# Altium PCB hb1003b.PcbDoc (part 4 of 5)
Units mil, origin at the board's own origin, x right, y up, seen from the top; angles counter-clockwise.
Board outline 2757 x 3548 mil, 2 copper layers (Top Layer, Bottom Layer); 120 components, 120 nets, 466 pads, 329 vias.
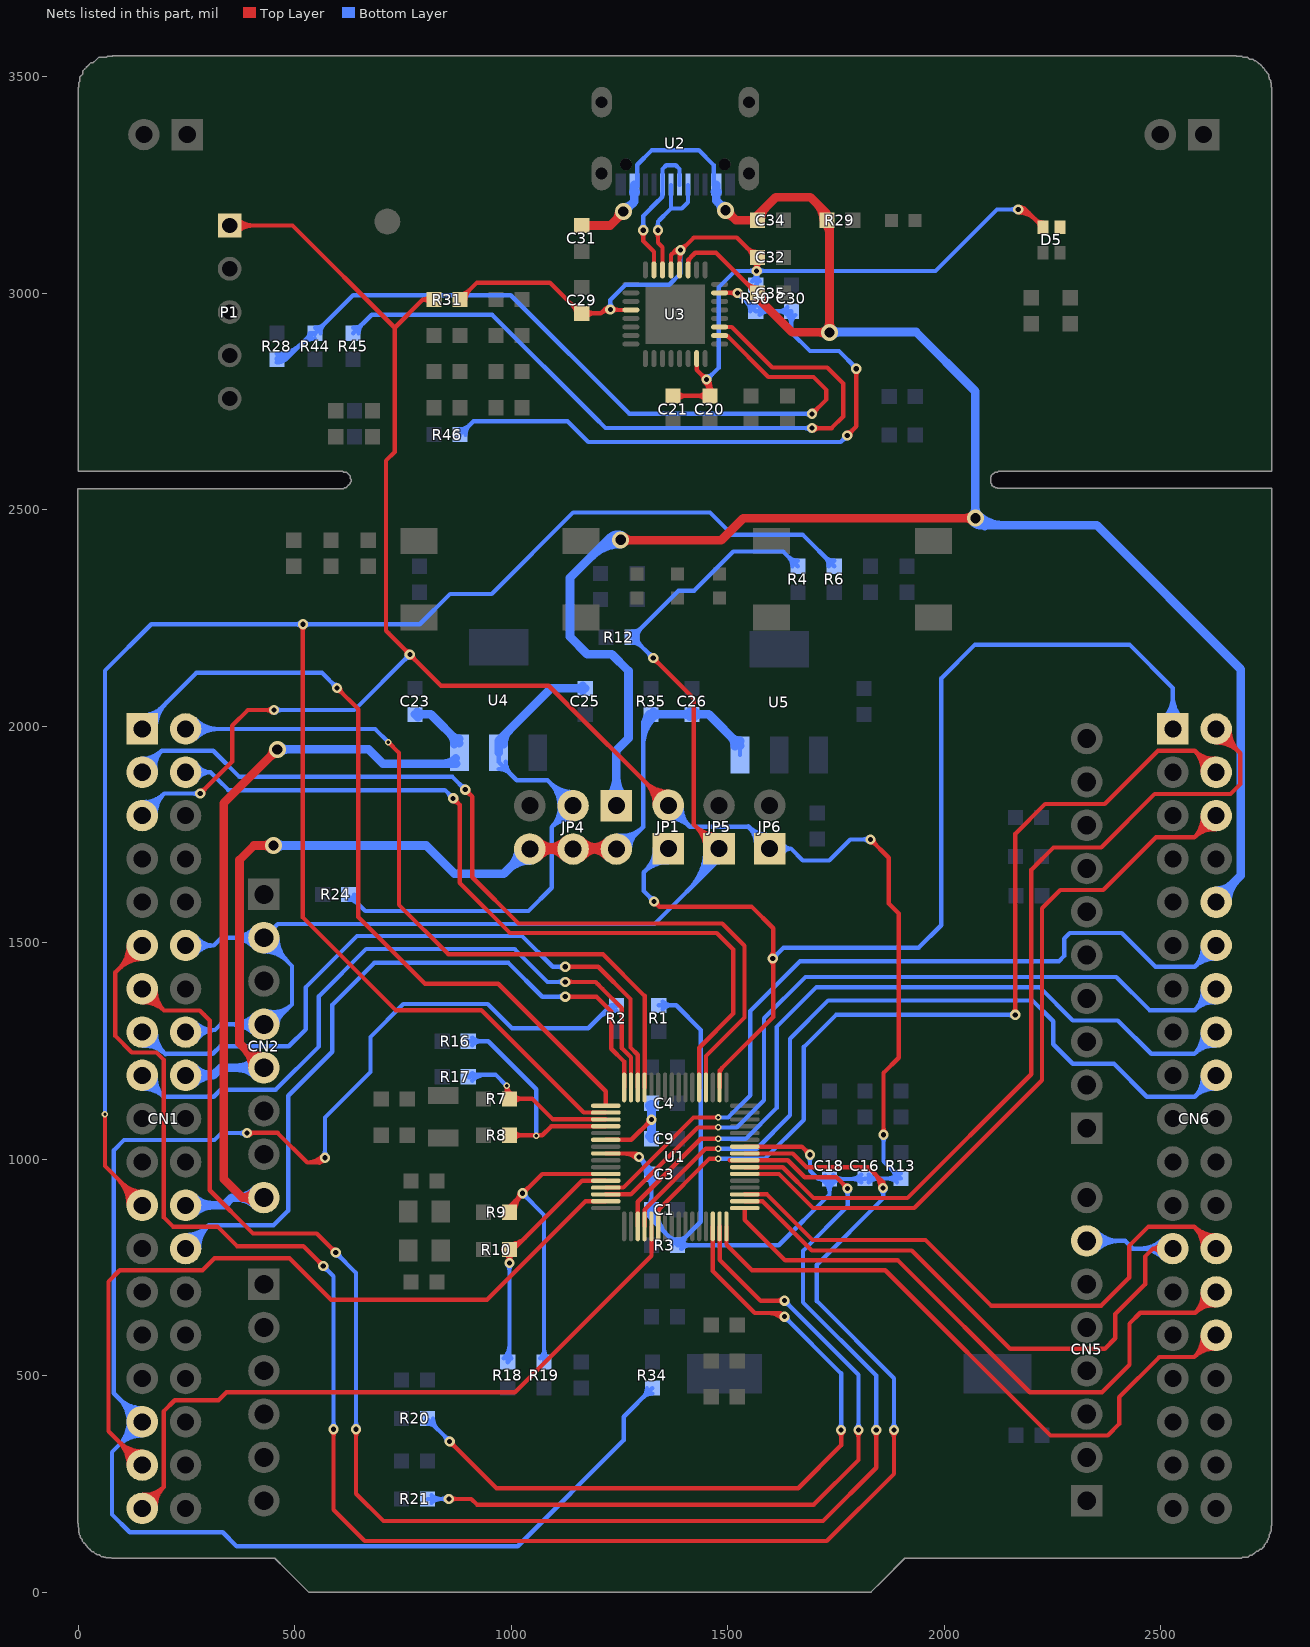
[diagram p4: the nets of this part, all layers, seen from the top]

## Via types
v1: diameter 23.62, hole 11.81, Top Layer to Bottom Layer, tented both sides, 290 vias
v2: diameter 39.37, hole 23.62, Top Layer to Bottom Layer, tented both sides, 29 vias
v3: diameter 15, hole 8, Top Layer to Bottom Layer, tented both sides, 10 vias

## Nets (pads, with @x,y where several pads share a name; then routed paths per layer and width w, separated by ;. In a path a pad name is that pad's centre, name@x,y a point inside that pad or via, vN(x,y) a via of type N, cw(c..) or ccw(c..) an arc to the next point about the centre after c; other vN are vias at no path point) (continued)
PB10: R20.2 U1.30 | length 1956.9
  Top Layer w10: v1@858,341.19 cw(c858,324.75) 869.63,336.37 cw(c881.25,348) v1@864.81,348 ; v1(858,348) 966,240 1663,240 1762,339 v1(1762,374) ; U1.30@1465.61,844.57 1465.61,741.39 1562.5,644.5 1622.5,644.5 v1(1631,636) ; 1594.04,644.5 cw(c1594.04,599.04) v1@1626.18,631.18 ; 1618.18,644.5 cw(c1618.18,623.18) v1@1633.25,638.25 ; v1@1757.18,369.18 cw(c1745.56,357.56) 1762,357.56 cw(c1778.44,357.56) v1@1766.82,369.18
  Bottom Layer w10: R20.2@805,401 v1@858.5,347.5 ; R20.2@807,388.5 cw(c807,363.16) 824.92,381.08 ; R20.2@819.5,401 ccw(c854.51,401) 829.75,376.25 ; v1@851.19,348 ccw(c834.75,348) 846.37,359.63 ccw(c858,371.25) v1@858,354.81 ; v1@1631,629.19 cw(c1631,612.75) 1642.63,624.37 cw(c1654.25,636) v1@1637.81,636 ; v1(1631,636) 1762,505 v1@1762,375 ; v1@1757.18,378.82 ccw(c1745.56,390.44) 1762,390.44 ccw(c1778.44,390.44) v1@1766.82,378.82
PB11: R21.2 U1.31 | length 1950
  Top Layer w10: v1(856,215) 908,215 921,202 1699,202 1802,305 v1(1802,374) ; v1@860.82,210.18 cw(c872.44,198.56) 872.44,215 cw(c872.44,231.44) v1@860.82,219.82 ; U1.31@1481.36,844.57 1481.36,767.64 1576,673 v1(1631,673) ; v1@1626.18,668.18 ccw(c1614.56,656.56) 1614.56,673 ccw(c1614.56,689.44) v1@1626.18,677.82 ; v1@1797.18,369.18 cw(c1785.56,357.56) 1802,357.56 cw(c1818.44,357.56) v1@1806.82,369.18
  Bottom Layer w10: R21.2@807,215 v1(856,215) ; R21.2@815.84,206.16 cw(c837.18,184.83) 837.18,215 cw(c837.18,245.18) R21.2@815.84,223.84 ; v1@851.18,210.18 ccw(c839.56,198.56) 839.56,215 ccw(c839.56,231.44) v1@851.18,219.82 ; v1@1631,666.19 cw(c1631,649.75) 1642.63,661.37 cw(c1654.25,673) v1@1637.81,673 ; v1(1631,673) 1802,502 v1(1802,374) ; v1@1797.18,378.82 ccw(c1785.56,390.44) 1802,390.44 ccw(c1818.44,390.44) v1@1806.82,378.82
PB12: CN6.30 U1.32 | length 1675.1
  Top Layer w10: U1.32@1497.11,844.57 1497.11,801.89 1556,743 1864,743 2245.42,361.58 2377.58,361.58 2404,388 2404,450 2497,543 2577.77,543 ; CN6.30@2596.62,591.74 cw(c2532.11,588.67) 2577.77,543 ; CN6.30@2606.61,592.21 cw(c2562.63,590.12) 2593.76,558.99 cw(c2624.89,527.86) CN6.30@2626.98,571.83 ; CN6.30@2625,595 CN6.30@2631,595 ; CN6.30@2626.51,561.85 ccw(c2623.44,497.34) 2577.77,543 ; CN6.30@2628,593.23 2577.77,543
PB13: CN6.28 U1.33 | length 1601.7
  Top Layer w10: U1.33@1539.43,886.89 1539.43,859.57 1633,766 1893,766 2197.42,461.58 2364.58,461.58 2428,525 2428,620 2453,645 2579.77,645 ; CN6.28@2596.68,690.78 cw(c2538.54,686.24) 2579.77,645 ; CN6.28@2606.65,691.56 cw(c2567.01,688.46) 2595.12,660.35 cw(c2623.24,632.24) CN6.28@2626.33,671.88 ; CN6.28@2625.55,661.91 ccw(c2621.01,603.77) 2579.77,645 ; CN6.28@2628,693.23 2579.77,645
PB14: CN5.7 CN6.25 U1.34 | length 1946.6
  Top Layer w10: U1.34@1539.43,902.64 1580.36,902.64 1694,789 1925,789 2152.42,561.58 2370.58,561.58 2395,586 2395,642 2464,711 2464,775 2482.23,793.23 ; CN6.25@2498.68,781.93 ccw(c2482.23,775.6) 2482.23,793.23 ; CN6.25@2498.68,804.52 cw(c2482.23,810.86) 2482.23,793.23 ; CN6.25@2528,793.23 2482.23,793.23
  Bottom Layer w10: CN5.7@2328,811 CN5.7@2329,811 2418,811 2431,798 2435.77,793.23 CN6.25@2528,793.23 ; CN5.7@2344.14,795.86 cw(c2380.71,759.29) 2380.71,811 cw(c2380.71,862.71) CN5.7@2344.14,826.14 ; CN5.7@2351.22,788.78 cw(c2404.85,735.15) 2404.85,811 cw(c2404.85,886.85) CN5.7@2351.22,833.22 ; CN6.25@2505.78,771.01 ccw(c2452.15,717.38) 2452.15,793.23 ccw(c2452.15,869.08) CN6.25@2505.78,815.44 ; CN6.25@2512.86,778.08 ccw(c2476.29,741.52) 2476.29,793.23 ccw(c2476.29,844.93) CN6.25@2512.86,808.37
PB15: CN6.26 U1.35 | length 1518.3
  Top Layer w10: U1.35@1539.43,918.39 1590.61,918.39 1696,813 1957,813 2108.42,661.58 2362.58,661.58 2427,726 2427,799 2472,844 2550,844 2577.23,844 ; CN6.26@2596.61,794.47 ccw(c2530.33,797.09) 2577.23,844 ; CN6.26@2606.6,794.07 ccw(c2561.42,795.86) 2593.39,827.84 ccw(c2625.37,859.81) CN6.26@2627.15,814.63 ; CN6.26@2626.76,824.62 cw(c2624.14,890.9) 2577.23,844 ; CN6.26@2628,793.23 2577.23,844
PC0: CN6.12 U1.13 | length 2024.9
  Top Layer w10: U1.13@1218.57,934.13 1259.13,934.13 1421,1096 v3(1478,1096)
  Bottom Layer w10: v3@1477,1096 v3(1478,1096) 1501,1096 1552,1147 1552,1342 1667,1457 2265,1457 2277,1469 2277,1509 2290,1522 2410,1522 2488,1444 2578.77,1444 ; CN6.12@2596.64,1491.27 cw(c2535.34,1487.43) 2578.77,1444 ; CN6.12@2606.62,1491.89 cw(c2564.84,1489.28) 2594.44,1459.67 cw(c2624.05,1430.06) CN6.12@2626.66,1471.85 ; CN6.12@2626.04,1461.87 ccw(c2622.2,1400.57) 2578.77,1444 ; CN6.12@2628,1492.54 CN6.12@2628,1493.23 ; CN6.12@2628,1498 CN6.12@2628,1493.23 ; 2578.77,1444 CN6.12@2628,1493.23
PC1: CN6.14 U1.14 | length 1988.3
  Top Layer w10: U1.14@1218.57,918.39 1276.39,918.39 1431,1073 v3(1478,1073)
  Bottom Layer w10: v3(1478,1073) 1521,1073 1584,1136 1584,1325 1679.58,1420.58 2329,1420.58 ; 2309.77,1420.58 2329,1420.58 ; 2348.23,1420.58 2338,1420.58 ; CN6.14@2596.64,1391.27 cw(c2535.34,1387.43) 2578.77,1344 ; CN6.14@2606.62,1391.89 cw(c2564.84,1389.28) 2594.44,1359.67 cw(c2624.05,1330.06) CN6.14@2626.66,1371.85 ; CN6.14@2625.61,1395.61 CN6.14@2628,1398 ; CN6.14@2626.04,1361.87 ccw(c2622.2,1300.57) 2578.77,1344 ; CN6.14@2628,1393.23 2578.77,1344 ; 2329,1420.58 2338,1420.58 ; 2338,1420.58 2397.42,1420.58 2474,1344 2578.77,1344
PC2: CN1.35 U1.15 | length 1961.4
  Top Layer w10: CN1.35@116.58,293.23 ccw(c40.73,293.23) 94.37,346.86 ccw(c148,400.49) CN1.35@148,324.65 ; CN1.35@126.58,293.23 ccw(c74.88,293.23) 111.44,329.79 ccw(c148,366.35) CN1.35@148,314.65 ; CN1.35@148,293.23 70,371.23 70,717 96,743 287,743 315,771 488,771 584,675 944,675 1171.64,902.64 U1.15@1218.57,902.64
PC3: CN6.16 U1.19 | length 1976.2
  Top Layer w10: U1.19@1292.39,844.57 1292.39,901.39 1438,1047 v3(1478,1047)
  Bottom Layer w10: v3(1478,1047) 1542,1047 1613,1118 1613,1305 1705,1397 2220,1397 2297,1320 2401,1320 2478,1243 2577.77,1243 ; CN6.16@2596.62,1291.74 cw(c2532.11,1288.67) 2577.77,1243 ; CN6.16@2606.61,1292.21 cw(c2562.63,1290.12) 2593.76,1258.99 cw(c2624.89,1227.86) CN6.16@2626.98,1271.83 ; CN6.16@2625.61,1295.61 CN6.16@2628,1298 ; CN6.16@2626.51,1261.85 ccw(c2623.44,1197.34) 2577.77,1243 ; CN6.16@2628,1293.23 2577.77,1243
PC4: CN6.18 U1.20 | length 2001
  Top Layer w10: U1.20@1308.05,874.09 cw(c1329.69,874.09) 1314.39,889.39 ; U1.20@1308.13,844.57 1308.13,883.13 1449,1024 v3(1478,1024)
  Bottom Layer w10: v3(1478,1024) 1567,1024 1644,1101 1644,1278 1732,1366 2204,1366 2252,1318 2252,1265 2297,1220 2392,1220 2468,1144 2578.77,1144 ; CN6.18@2596.64,1191.27 cw(c2535.34,1187.43) 2578.77,1144 ; CN6.18@2606.62,1191.89 cw(c2564.84,1189.28) 2594.44,1159.67 cw(c2624.05,1130.06) CN6.18@2626.66,1171.85 ; CN6.18@2625.61,1195.61 CN6.18@2628,1198 ; CN6.18@2626.04,1161.87 ccw(c2622.2,1100.57) 2578.77,1144 ; CN6.18@2628,1193.23 2578.77,1144
PC5: CN1.37 U1.21 | length 1763.9
  Top Layer w10: CN1.37@148,193.23 197.42,242.65 ; CN1.37@149.28,214.61 ccw(c151.79,256.81) 181.69,226.91 ccw(c211.58,197.02) CN1.37@169.38,194.5 ; CN1.37@149.87,224.59 ccw(c153.57,286.49) 197.41,242.64 ; CN1.37@179.36,195.1 cw(c241.27,198.79) 197.42,242.64 ; U1.21@1323.88,844.57 1323.88,776.88 1008.58,461.58 342.58,461.58 324,443 223.11,443 197.42,417.3 197.42,242.65
PC6: CN6.4 U1.22 | length 2385
  Top Layer w10: U1.22@1339.57,874.04 cw(c1343.95,878.31) 1339.63,882.63 ; U1.22@1339.55,874.09 cw(c1359.97,874.09) 1345.53,888.53 ; U1.22@1339.63,844.57 1339.63,882.63 ; v3(1478,1001) 1458,1001 1339.63,882.63 ; v1@2159.18,1337.82 ccw(c2147.56,1349.44) 2164,1349.44 ccw(c2180.44,1349.44) v1@2168.82,1337.82 ; v1(2164,1333) 2164,1751 2233,1820 2370.58,1820 2493.58,1943 2578.23,1943 ; CN6.4@2596.63,1894.93 ccw(c2533.59,1898.36) 2578.23,1943 ; CN6.4@2606.61,1894.39 ccw(c2563.64,1896.72) 2594.07,1927.16 ccw(c2624.5,1957.59) CN6.4@2626.84,1914.61 ; CN6.4@2626.3,1924.6 cw(c2622.87,1987.64) 2578.23,1943 ; CN6.4@2628,1893.23 2578.23,1943
  Bottom Layer w10: v3(1478,1001) 1586,1001 1676,1091 1676,1259 1750,1333 v1(2164,1333) ; v1@2159.18,1328.18 ccw(c2147.56,1316.56) 2147.56,1333 ccw(c2147.56,1349.44) v1@2159.18,1337.82
PC7: CN6.6 U1.38 | length 2004.7
  Top Layer w10: 1574.31,965.63 U1.38@1539.43,965.63 1618.37,965.63 1697,887 1931,887 2226,1182 2226,1272 2226,1579 2259.5,1612.5 ; 2266.42,1619.42 2259.5,1612.5 ; 2315,1621.42 2326,1621.42 ; 2491,1743 2510,1743 ; 2575,1743 2555,1743 ; CN6.6@2596.62,1791.74 cw(c2532.11,1788.67) 2577.77,1743 ; CN6.6@2606.61,1792.21 cw(c2562.63,1790.12) 2593.76,1758.99 cw(c2624.89,1727.86) CN6.6@2626.98,1771.83 ; CN6.6@2626.51,1761.85 ccw(c2623.44,1697.34) 2577.77,1743 ; CN6.6@2628,1793.23 2577.77,1743 ; 2259.5,1612.5 2268.42,1621.42 2326,1621.42 ; 2326,1621.42 2367.42,1621.42 2489,1743 2510,1743 ; 2510,1743 2555,1743 ; 2555,1743 2577.77,1743
PC8: CN6.2 U1.39 | length 2233.4
  Top Layer w10: U1.39@1539.43,981.38 1539.81,981 1627,981 1698,910 1915,910 2200.81,1195.81 2200.81,1667.81 2222,1689 2230.5,1697.5 2252.58,1719.58 2292,1719.58 ; 2274.58,1719.58 2292,1719.58 ; 2349.58,1719.58 2331,1719.58 ; CN6.2@2628,1961.81 cw(c2628,1885.96) 2681.63,1939.6 cw(c2735.27,1993.23) CN6.2@2659.42,1993.23 ; CN6.2@2628,1971.81 cw(c2628,1920.11) 2664.56,1956.67 cw(c2701.12,1993.23) CN6.2@2649.42,1993.23 ; CN6.2@2628,1993.23 2684,1937.23 2684,1866 2661,1843 2486,1843 2362.58,1719.58 2331,1719.58 ; 2292,1719.58 2331,1719.58
PC9: CN6.1 JP1.1 U1.50 | length 3117.5
  Top Layer w10: v1@1330,1588.19 cw(c1330,1571.75) 1341.63,1583.37 cw(c1353.25,1595) v1@1336.81,1595 ; v1(1330,1595) 1342,1583 1555,1583 1605,1533 1605,1328 1481.36,1204.36 U1.50@1481.36,1165.43 ; U1.50@1481.28,1194.96 cw(c1503.79,1194.96) 1487.88,1210.88 ; v1@1599.18,1458.18 cw(c1585.14,1444.14) 1605,1444.14 ; v1@1599.18,1467.82 ccw(c1585.14,1481.86) 1605,1481.86 ; 1605,1448.97 cw(c1618.03,1448.97) v1@1608.82,1458.18 ; 1605,1477.03 ccw(c1618.03,1477.03) v1@1608.82,1467.82
  Bottom Layer w10: 1305.95,1661.95 cw(c1363,1604.91) JP1.1@1363,1685.58 ; 1310.78,1666.78 ccw(c1260.56,1717) JP1.1@1331.58,1717 ; 1323.02,1679.02 cw(c1363,1639.05) JP1.1@1363,1695.58 ; v1@1323.19,1595 ccw(c1306.75,1595) 1318.37,1606.63 ccw(c1330,1618.25) v1@1330,1601.81 ; JP1.1@1327.85,1683.85 ccw(c1294.71,1717) JP1.1@1341.58,1717 ; v1(1330,1595) 1306,1619 1306,1662 JP1.1@1362,1718 ; v1(1604,1463) 1629,1488 1941,1488 1993,1540 1993,2110 2071,2188 2428,2188 2528,2088 CN6.1@2528,1993.23 ; v1@1604,1469.81 ccw(c1604,1486.25) 1615.63,1474.63 ccw(c1627.25,1463) v1@1610.81,1463 ; CN6.1@2505.78,2015.44 ccw(c2452.15,2069.08) 2528,2069.08 ccw(c2603.85,2069.08) CN6.1@2550.22,2015.44 ; CN6.1@2512.86,2008.37 ccw(c2476.29,2044.93) 2528,2044.93 ccw(c2579.71,2044.93) CN6.1@2543.14,2008.37
PC10: CN1.3 U1.52 | length 2285.3
  Top Layer w10: v1@894,1846.19 cw(c894,1829.75) 905.63,1841.37 cw(c917.25,1853) v1@900.81,1853 ; v1(894,1853) 910,1837 910,1651 1017,1544 1487.5,1544 1539,1492.5 1539,1327 1449.87,1237.87 U1.52@1449.87,1165.43
  Bottom Layer w10: CN1.3@148,1898 193,1943 ; CN1.3@148.16,1914.64 ccw(c148.44,1953.76) 176.1,1926.1 ; CN1.3@148.23,1924.64 ccw(c148.68,1987.31) 193,1943 ; CN1.3@169.1,1896.9 cw(c205.52,1903.24) 179.38,1929.38 ; CN1.3@178.95,1898.62 cw(c228.72,1907.28) 193,1943 ; v1@887.19,1853 ccw(c870.75,1853) 882.37,1864.63 ccw(c894,1876.25) v1@894,1859.81 ; v1(894,1853) 864.37,1882.63 372.37,1882.63 312,1943 193,1943
PC11: CN1.4 U1.53 | length 2068.2
  Top Layer w10: v1@866,1826.19 cw(c866,1809.75) 877.63,1821.37 cw(c889.25,1833) v1@872.81,1833 ; v1(866,1833) 881,1818 881,1638 997,1522 1475,1522 1513,1484 1513,1336 1434.12,1257.12 U1.53@1434.12,1165.43
  Bottom Layer w10: CN1.4@248,1893.23 305.77,1893.23 ; CN1.4@265.98,1881.59 cw(c287.38,1867.73) 287.38,1893.23 cw(c287.38,1918.73) CN1.4@265.98,1904.87 ; CN1.4@274.37,1876.15 cw(c305.77,1855.82) 305.77,1893.23 ; CN1.4@274.37,1910.3 ccw(c305.77,1930.63) 305.77,1893.23 ; v1@859.19,1833 ccw(c842.75,1833) 854.37,1844.63 ccw(c866,1856.25) v1@866,1839.81 ; v1(866,1833) 847,1852 347,1852 322.5,1876.5 305.77,1893.23
PC12: CN1.1 U1.1 | length 2089.2
  Top Layer w10: v1@598,2081.19 cw(c598,2064.75) 609.63,2076.37 cw(c621.25,2088) v1@604.81,2088 ; v1(598,2088) 647,2039 647,1559 801,1405 923,1405 970,1405 1218.57,1156.43 U1.1@1218.57,1123.11
  Bottom Layer w10: CN1.1@148,1998 273,2123 563,2123 v1(598,2088) ; CN1.1@148,2014.65 ccw(c148,2054.83) CN1.1@176.42,2026.42 ; CN1.1@148,2024.65 ccw(c148,2088.97) 193.49,2043.49 ; CN1.1@169.42,1993.23 cw(c232.64,1993.23) 187.94,2037.94 ; CN1.1@179.42,1993.23 cw(c266.79,1993.23) 205.01,2055.01 ; v1@591.19,2088 ccw(c574.75,2088) 586.37,2099.63 ccw(c598,2111.25) v1@598,2094.81
PC13: CN1.23 R6.1 U1.2 | length 5039.7
  Top Layer w10: v3@62,1103 62,984 CN1.23@148,898 ; 90.99,955.01 cw(c29.21,893.23) CN1.23@116.58,893.23 ; 102.51,943.49 ccw(c148,988.97) CN1.23@148,924.65 ; 108.06,937.94 cw(c63.36,893.23) CN1.23@126.58,893.23 ; 119.58,926.42 ccw(c148,954.83) CN1.23@148,914.65 ; v1@514.18,2230.18 cw(c502.56,2218.56) 519,2218.56 cw(c535.44,2218.56) v1@523.82,2230.18 ; v1(519,2235) 519,1558 733,1344 931,1344 1167.64,1107.36 U1.2@1218.57,1107.36
  Bottom Layer w10: v3(62,1103.99) 62,2128 169,2235 v1(519,2235) 789,2235 859,2305 955,2305 1143,2493 1459,2493 1510,2442 1673,2442 R6.1@1746,2369 ; v1@514.18,2230.18 ccw(c502.56,2218.56) 502.56,2235 ccw(c502.56,2251.44) v1@514.18,2239.82 ; v1@523.82,2230.18 cw(c535.44,2218.56) 535.44,2235 cw(c535.44,2251.44) v1@523.82,2239.82 ; R6.1@1733.5,2369 ccw(c1703.32,2369) 1724.66,2390.34 ccw(c1746,2411.68) R6.1@1746,2381.5
PC14: R7.1 R17.2 U1.3 | length 516.3
  Top Layer w10: R7.1@1001.61,1150.17 cw(c1011.07,1169) v3(990,1169) 990,1139 1049,1139 1096.39,1091.61 U1.3@1218.57,1091.61 ; R7.1@1004.84,1130.16 cw(c1026.18,1108.82) 1026.18,1139 cw(c1026.18,1169.18) R7.1@1004.84,1147.84
  Bottom Layer w10: R17.2@901,1190 906,1195 964,1195 v3(990,1169) ; R17.2@902.77,1188.23 cw(c919.1,1171.9) 919.1,1195 cw(c919.11,1208.11) R17.2@909.84,1198.84 ; R17.2@909.84,1181.16 cw(c943.25,1147.75) 943.25,1195
PC15: R8.1 R16.2 U1.4 | length 655.8
  Top Layer w10: R8.1@990,1055 1072,1055 1092.87,1075.87 U1.4@1218.57,1075.87 ; R8.1@1004.84,1046.16 cw(c1026.18,1024.82) 1026.18,1055 cw(c1026.18,1085.18) R8.1@1004.84,1063.84 ; 1049.55,1055 cw(c1049.55,1045.55) v3@1056.23,1052.23 ; v3@1059.77,1052.23 cw(c1066.45,1045.55) 1066.45,1055
  Bottom Layer w10: R16.2@901,1272 947,1272 1058,1161 v3@1058,1055 ; R16.2@909.84,1263.16 cw(c931.18,1241.82) 931.18,1272 cw(c931.18,1302.18) R16.2@909.84,1280.84
  other v3: 1058,1054
PD0: CN1.13 U1.40 | length 4247.1
  Top Layer w10: CN1.13@148,1393.23 198.23,1343 ; CN1.13@148,1398 CN1.13@150.39,1395.61 ; CN1.13@149.02,1371.83 cw(c151.11,1327.86) 182.24,1358.99 cw(c213.37,1390.12) CN1.13@169.39,1392.21 ; CN1.13@149.49,1361.85 cw(c152.56,1297.34) 198.23,1343 ; CN1.13@179.38,1391.74 ccw(c243.89,1388.67) 198.23,1343 ; 302,1322 291,1333 ; v1@588.19,784 ccw(c571.75,784) 583.37,795.63 ccw(c595,807.25) v1@595,790.81 ; v1(595,784) 551,828 404,828 304,928 304,1320 291,1333 ; v1@637.01,371.18 cw(c625.38,359.56) 641.82,359.56 cw(c658.27,359.56) v1@646.64,371.18 ; v1(641.82,376) 641.82,227.18 705,164 1720,164 1843,287 v1(1843,374) ; 1504.55,997.13 U1.40@1539.43,997.13 1638.87,997.13 1678,958 1751,958 v1(1777,932) ; v1@1770.19,932 ccw(c1753.75,932) 1765.37,943.63 ccw(c1777,955.25) v1@1777,938.81 ; v1@1838.18,369.18 cw(c1826.56,357.56) 1843,357.56 cw(c1859.44,357.56) v1@1847.82,369.18 ; 198.23,1343 281,1343 291,1333
  Bottom Layer w10: v1@595,777.19 cw(c595,760.75) 606.63,772.37 cw(c618.25,784) v1@601.81,784 ; v1(595,784) 641.82,737.18 v1(641.82,376) ; v1@637.01,380.82 ccw(c625.38,392.44) 641.82,392.44 ccw(c658.27,392.44) v1@646.64,380.82 ; v1@1772.18,927.18 cw(c1760.56,915.56) 1777,915.56 cw(c1793.44,915.56) v1@1781.82,927.18 ; v1(1777,932) 1777,891 1674,788 1674,669 1843,500 v1(1843,374) ; v1@1838.18,378.82 ccw(c1826.56,390.44) 1843,390.44 ccw(c1859.44,390.44) v1@1847.82,378.82
PD1: CN1.11 U1.41 | length 4758.4
  Top Layer w10: CN1.11@116.58,1493.23 cw(c40.73,1493.23) 94.37,1439.6 cw(c148,1385.96) CN1.11@148,1461.81 ; CN1.11@126.58,1493.23 cw(c74.88,1493.23) 111.44,1456.67 cw(c148,1420.11) CN1.11@148,1471.81 ; CN1.11@145.61,1495.61 CN1.11@148,1498 ; CN1.11@148,1493.23 86,1431.23 86,1284 124,1246 181,1246 198,1229 198,865 219,844 322,844 367,799 520,799 v1(566,753) ; v1@559.19,753 ccw(c542.75,753) 554.37,764.63 ccw(c566,776.25) v1@566,759.81 ; v1@585.01,371.18 cw(c573.38,359.56) 589.82,359.56 cw(c606.27,359.56) v1@594.64,371.18 ; v1(589.82,376) 589.82,190.18 662,118 709,118 ; 682,118 709,118 ; U1.41@1539.43,1012.87 1650.13,1012.87 1682,981 1825,981 1859,947 ; 1837.47,968.53 cw(c1801.95,933) v1@1852.19,933 ; 1854.54,951.46 cw(c1836.09,933) v1@1862.19,933 ; v1@1854.8,938.36 ccw(c1848.02,947) 1859,947 ; v1(1859,933) 1859,947 ; v1@1863.2,938.36 cw(c1869.98,947) 1859,947 ; v1@1879.18,369.18 cw(c1867.56,357.56) 1884,357.56 cw(c1900.44,357.56) v1@1888.82,369.18 ; v1(1884,374) 1884,273 1729,118 709,118
  Bottom Layer w10: v1@566,746.19 cw(c566,729.75) 577.63,741.37 cw(c589.25,753) v1@572.81,753 ; v1(566,753) 589.82,729.18 v1(589.82,376) ; v1@585.01,380.82 ccw(c573.38,392.44) 589.82,392.44 ccw(c606.27,392.44) v1@594.64,380.82 ; v1@1854.18,928.18 cw(c1842.56,916.56) 1859,916.56 cw(c1875.44,916.56) v1@1863.82,928.18 ; v1(1859,933) 1859,909 1706,756 1706,672 1884,494 v1(1884,374) ; v1@1879.18,378.82 ccw(c1867.56,390.44) 1884,390.44 ccw(c1900.44,390.44) v1@1888.82,378.82
PD2: CN1.2 U1.61 | length 1932.8
  Top Layer w10: v3(716,1963) 741,1938 741,1587 855,1473 1212,1473 1308.13,1376.87 U1.61@1308.13,1165.43
  Bottom Layer w10: CN1.2@248,1993.23 685.77,1993.23 v3(716,1963) ; CN1.2@263.14,1978.08 cw(c299.71,1941.52) 299.71,1993.23 cw(c299.71,2044.93) CN1.2@263.14,2008.37 ; CN1.2@270.22,1971.01 cw(c323.85,1917.38) 323.85,1993.23 cw(c323.85,2069.08) CN1.2@270.22,2015.44
PD3: CN1.15 U1.62 | length 1833.5
  Top Layer w10: v1(1125,1444) 1201,1444 1275.42,1369.58 1275.42,1257.65 1292.39,1240.68 U1.62@1292.39,1165.43 ; v1@1129.82,1439.18 cw(c1141.44,1427.56) 1141.44,1444 cw(c1141.44,1460.44) v1@1129.82,1448.82
  Bottom Layer w10: CN1.15@148,1293.23 148,1295.67 200.67,1243 311,1243 328.42,1260.42 486.42,1260.42 526,1300 526,1397 644,1515 1025,1515 1096,1444 v1(1125,1444) ; CN1.15@149.11,1271.84 cw(c151.64,1223.31) 186,1257.67 ; CN1.15@149.63,1261.85 cw(c153.21,1193.1) 201.89,1241.78 ; CN1.15@169.42,1293.23 ccw(c215.23,1293.23) 182.84,1260.83 ; CN1.15@179.42,1293.23 ccw(c249.37,1293.23) 199.91,1243.76 ; v1@1120.18,1439.18 ccw(c1108.56,1427.56) 1108.56,1444 ccw(c1108.56,1460.44) v1@1120.18,1448.82
PD4: CN1.17 U1.63 | length 1831.2
  Top Layer w10: v1(1125,1409) 1195.05,1409 1210.02,1394.02 ; v1@1129.82,1404.18 cw(c1141.44,1392.56) 1141.44,1409 cw(c1141.44,1425.44) v1@1129.82,1413.82 ; 1199.05,1405 1210.02,1394.02 ; U1.63@1276.64,1165.43 1276.64,1235.21 1255.73,1256.12 1255.73,1348.32 1210.02,1394.02
  Bottom Layer w10: CN1.17@148,1193.23 197.23,1144 ; CN1.17@148,1198 CN1.17@150.39,1195.61 ; CN1.17@149.34,1171.85 cw(c151.95,1130.06) 181.56,1159.67 cw(c211.16,1189.28) CN1.17@169.38,1191.89 ; CN1.17@149.96,1161.87 cw(c153.8,1100.57) 197.23,1144 ; CN1.17@179.36,1191.27 ccw(c240.66,1187.43) 197.23,1144 ; v1@1120.18,1404.18 ccw(c1108.56,1392.56) 1108.56,1409 ccw(c1108.56,1425.44) v1@1120.18,1413.82 ; v1(1125,1409) 1084,1409 1008,1485 665,1485 556,1376 556,1260 456.42,1160.42 329.42,1160.42 313,1144 197.23,1144
PD5: CN1.26 U1.64 | length 1967.3
  Top Layer w10: v1(1125,1375) 1197,1375 1231.36,1340.64 1231.36,1269 ; v1@1129.82,1370.18 cw(c1141.44,1358.56) 1141.44,1375 cw(c1141.44,1391.44) v1@1129.82,1379.82 ; 1231.36,1263.86 1231.36,1269 ; U1.64@1260.89,1165.43 1260.89,1225.11 1231.36,1254.64 1231.36,1269
  Bottom Layer w10: CN1.26@248,793.23 301.77,847 451,847 485,881 485,1146 587,1248 587,1356 684,1453 994,1453 1072,1375 v1(1125,1375) v1@1126,1375 ; CN1.26@248,814.65 ccw(c248,866.35) 284.56,829.79 ccw(c321.12,793.23) CN1.26@269.42,793.23 ; CN1.26@248,824.65 ccw(c248,900.49) 301.63,846.86 ccw(c355.27,793.23) CN1.26@279.42,793.23 ; v1@1120.18,1370.18 ccw(c1108.56,1358.56) 1108.56,1375 ccw(c1108.56,1391.44) v1@1120.18,1379.82
PF0: R9.2 R19.2 U1.11 | length 882.1
  Top Layer w10: R9.2@982,888 994,888 1071.63,965.63 U1.11@1218.57,965.63 ; R9.2@998.5,877 cw(c1035.92,877) 1009.46,903.46 ; R9.2@1008.5,877 cw(c1070.07,877) v1@1026.53,920.53 ; 1013.67,907.67 ccw(c1000.33,921) v1@1019.19,921 ; 1016.08,910.08 cw(c1026,900.16) v1@1026,914.19 ; v1@1026,927.81 ccw(c1026,946.67) 1039.33,933.33 ; v1@1032.81,921 cw(c1046.84,921) 1036.92,930.92
  Bottom Layer w10: v1@1026,914.19 cw(c1026,897.75) 1037.63,909.37 cw(c1049.25,921) v1@1032.81,921 ; v1(1026,921) 1076,871 R19.2@1076,531 ; R19.2@1067.16,539.84 ccw(c1045.82,561.18) 1076,561.18 ccw(c1106.18,561.18) R19.2@1084.84,539.84
PF1: R10.2 R18.2 U1.12 | length 780.1
  Top Layer w10: R10.2@983,791 R10.2@996,791 ; R10.2@987.16,782.16 cw(c965.82,760.82) 996,760.82 cw(c1026.18,760.82) R10.2@1004.84,782.16 ; v1@991.18,764.82 ccw(c979.56,776.44) 996,776.44 ccw(c1012.44,776.44) v1@1000.82,764.82 ; v1(996,760) R10.2@996,791 ; R10.2@996,793.5 ccw(c996,821.26) 1015.63,801.63 ; R10.2@996,803.5 ccw(c996,855.4) 1032.7,818.7 ; U1.12@1218.57,949.88 1163.88,949.88 1005,791 R10.2@996,791
  Bottom Layer w10: R18.2@983.16,539.84 ccw(c952.16,570.84) 996,570.84 ; v1@991.18,755.18 cw(c979.56,743.56) 996,743.56 cw(c1012.44,743.56) v1@1000.82,755.18 ; R18.2@992,539 R18.2@992,531 996,535 v1(996,760) ; 996,551.52 ccw(c1012.52,551.52) R18.2@1000.84,539.84
PRG_NRST: C30.1 R30.2 R46.1 U3.7 | length 1921.2
  Top Layer w10: U3.7@1479.39,3000.21 v1@1523,3000.21 ; 1506.04,3000.21 cw(c1506.04,2983.04) v1@1518.18,2995.18 ; 1507.07,3000.21 ccw(c1507.07,3015.93) v1@1518.18,3004.82 ; v1@1776,2671 1797,2692 v1(1797,2825) ; v1@1776.18,2677.81 ccw(c1776.18,2693.81) 1787.5,2682.5 ; v1@1782.99,2671 cw(c1799.88,2671) 1787.94,2682.94 ; v1@1792.18,2820.18 cw(c1780.56,2808.56) 1797,2808.56 cw(c1813.44,2808.56) v1@1801.82,2820.18
  Bottom Layer w10: R46.1@882,2673 913,2704 1028,2704 ; R46.1@882,2685.5 ccw(c882,2715.68) 903.34,2694.34 ccw(c924.68,2673) R46.1@894.5,2673 ; 1043,2704 1028,2704 ; v1@1523,2993.19 cw(c1523,2976.75) 1534.63,2988.37 cw(c1546.25,3000) v1@1529.81,3000 ; v1(1523,3000) R30.2@1565,2958 C30.1@1647,2958 1647,2909 1690,2866 1757,2866 v1@1797,2826 ; R30.2@1552.5,2958 ccw(c1522.32,2958) 1543.66,2979.34 ccw(c1565,3000.68) R30.2@1565,2970.5 ; R30.2@1573.84,2949.16 cw(c1595.18,2927.82) 1595.18,2958 cw(c1595.18,2988.18) R30.2@1573.84,2966.84 ; C30.1@1638.16,2966.84 cw(c1616.82,2988.18) 1616.82,2958 cw(c1616.82,2927.82) 1638.16,2949.16 cw(c1616.82,2927.82) 1647,2927.82 cw(c1677.18,2927.82) C30.1@1655.84,2949.16 ; v1@1769.37,2671 cw(c1752.93,2671) 1764.56,2659.37 cw(c1776.18,2647.75) v1@1776.18,2664.19 ; v1(1776.18,2671) 1761.18,2656 1178,2656 1130,2704 1028,2704 ; 1784.67,2838.33 cw(c1771.33,2825) v1@1790.19,2825 ; 1787.08,2835.92 ccw(c1797,2845.84) v1@1797,2831.81
PRG_SWCLK: R28.1 R44.1 U3.2 | length 2114.2
  Top Layer w10: U3.2@1479.39,2901.79 1480.57,2900.61 1499.27,2900.61 1593.88,2806 1698,2806 1728,2776 1728,2754 v1(1695,2721) ; U3.2@1495.54,2901.28 cw(c1495.54,2893.87) 1500.78,2899.11 ; v1@1695,2727.81 ccw(c1695,2744.25) 1706.63,2732.63 ccw(c1718.25,2721) v1@1701.81,2721
  Bottom Layer w10: R28.1@459,2839.5 ccw(c459,2872.1) 482.05,2849.05 ; R28.1@459,2847 479,2847 ; R28.1@459,2849.5 ccw(c459,2906.24) 499.12,2866.12 ; R28.1@459,2859.5 ccw(c459,2940.38) 516.19,2883.19 ; 480,2847 R44.1@540,2907 ; 513.71,2880.71 cw(c547,2847.42) R44.1@547,2894.5 ; R44.1@530.61,2897.61 ccw(c521.22,2907) R44.1@534.5,2907 ; R44.1@530.78,2897.78 cw(c547,2881.57) R44.1@547,2904.5 ; R44.1@539,2907 R44.1@547,2907 635,2995 944,2995 ; R44.1@547,2919.5 ccw(c547,2949.68) 568.34,2928.34 ccw(c589.68,2907) R44.1@559.5,2907 ; 975,2995 944,2995 ; v1@1690.18,2716.18 ccw(c1678.56,2704.56) 1678.56,2721 ccw(c1678.56,2737.44) v1@1690.18,2725.82 ; v1@1694,2721 1273,2721 999,2995 944,2995
PRG_SWDIO: R45.1 U3.3 | length 1798.5
  Top Layer w10: U3.3@1479.39,2921.47 1509.53,2921.47 1603,2828 1730,2828 1767,2791 1767,2715 1740,2688 v1(1695,2688) ; v1@1699.82,2683.18 cw(c1711.44,2671.56) 1711.44,2688 cw(c1711.44,2704.44) v1@1699.82,2692.82
  Bottom Layer w10: R45.1@635,2907 678,2950 956,2950 1192,2714 ; R45.1@635,2919.5 ccw(c635,2949.68) 656.34,2928.34 ccw(c677.68,2907) R45.1@647.5,2907 ; 1200,2706 1192,2714 ; 1678.1,2688.19 cw(c1678.1,2671.1) v1@1690.18,2683.18 ; 1679.01,2688.19 ccw(c1679.01,2703.99) v1@1690.18,2692.82 ; v1@1696,2688.19 1217.81,2688.19 1192,2714
USB_DM: U2.A7 U2.B7 U3.15 | length 413.6
  Top Layer w10: v1@1300.18,3140.18 cw(c1288.56,3128.56) 1305,3128.56 cw(c1321.44,3128.56) v1@1309.82,3140.18 ; v1(1305,3145) 1305,3120 1329.79,3095.21 U3.15@1329.79,3051.39
  Bottom Layer w10: v1@1300.18,3149.82 ccw(c1288.56,3161.44) 1305,3161.44 ccw(c1321.44,3161.44) v1@1309.82,3149.82 ; v1(1305,3145) 1305,3178 1339.81,3212.81 1340.17,3212.81 1349.39,3222.03 1349.39,3249.4 1349.39,3286.39 1358,3295 1380,3295 1388.76,3286.24 U2.A7@1388.76,3249.4 ; 1344.44,3217.08 ccw(c1333.67,3227.85) U2.B7@1348.66,3230.56
USB_DP: U2.A6 U2.B6 U3.14 | length 383.6
  Top Layer w10: v1@1334.18,3140.18 cw(c1322.56,3128.56) 1339,3128.56 cw(c1355.44,3128.56) v1@1343.82,3140.18 ; v1(1339,3145) 1339,3116 1349.47,3105.53 U3.14@1349.47,3051.39
  Bottom Layer w10: v1@1334.18,3149.82 ccw(c1322.56,3161.44) 1339,3161.44 ccw(c1355.44,3161.44) v1@1343.82,3149.82 ; v1(1339,3145) 1339,3165 1364.5,3190.5 ; 1342,3168 1364.5,3190.5 ; U2.A6@1369.08,3249.4 1369.08,3195.08 ; U2.B6@1408.45,3249.4 1408.45,3209.45 1394.08,3195.08 1369.08,3195.08 ; 1364.5,3190.5 1369.08,3195.08
VBAT: CN1.33 R2.2 R34.1 | length 4550.3
  Top Layer w10: v1(390,1060) 390.42,1060.42 460.58,1060.42 529,992 ; v1@394.82,1055.18 cw(c407.45,1042.55) 407.45,1060.42 ; v1@394.82,1064.82 ccw(c405.44,1075.44) 405.44,1060.42 ; 552.02,992 ccw(c552.02,1019.79) v1@572.33,1000.82 ; 557.5,991.5 cw(c568.88,980.12) v1@569.67,996.2 ; 559.08,993.08 ccw(c549.16,1003) v1@563.19,1003 ; v1@565.02,1007.65 cw(c529,1041.28) 529,992 ; v1(570,1003) 569,1003 558,992 529,992
  Bottom Layer w10: CN1.33@148,361.81 ccw(c148,285.96) 94.37,339.6 ccw(c40.73,393.23) 116.58,393.23 ccw(c40.73,393.23) 94.37,446.86 ccw(c148,500.49) CN1.33@148,424.65 ; CN1.33@148,371.81 ccw(c148,320.1) 111.44,356.67 ccw(c74.88,393.23) 126.58,393.23 ccw(c74.88,393.23) 111.44,429.79 ccw(c148,466.35) CN1.33@148,414.65 ; v1@385.18,1055.18 ccw(c373.56,1043.56) 373.56,1060 ccw(c373.56,1076.44) v1@385.18,1064.82 ; v1(390,1060) 331,1060 315,1044 106,1044 82,1020 82,459.23 CN1.33@148,393.23 78,323.23 78,179 119,138 334,138 366,106 1015,106 1260,351 1260,405 R34.1@1326,471 ; v1@565.18,1007.82 ccw(c553.56,1019.44) 570,1019.44 ccw(c586.44,1019.44) v1@574.82,1007.82 ; v1(570,1003) 570,1096 675,1201 675,1282 751,1358 946,1358 1002,1302 1178,1302 1231,1355 R2.2@1243,1355 ; 1201.18,1325.18 cw(c1243,1283.35) R2.2@1243,1342.5 ; 1218.25,1342.25 cw(c1243,1317.49) R2.2@1243,1352.5 ; R34.1@1313.5,471 cw(c1283.32,471) 1304.66,449.66 cw(c1326,428.32) R34.1@1326,458.5
VBUS_5V: C31.2 C34.2 C35.1 CN6.10 JP4.1 R29.1 U2.A4 U2.A9 U2.B4 U2.B9 U3.11 | length 6402.1
  Top Layer w10: U3.11@1408.53,3051.39 1408.53,3076.53 1425,3093 1473,3093 C35.1@1566,3000 ; U3.11@1409.04,3067.54 cw(c1431.98,3067.54) 1415.76,3083.76 ; 1542.54,3023.46 ccw(c1569,3049.92) C35.1@1569,3012.5 ; 1549.78,3016.21 cw(c1533.57,3000) C35.1@1556.5,3000
  Top Layer w20: C31.2@1163,3156 1229,3156 v2@1259.5,3186.5 ; C31.2@1168.3,3150.7 cw(c1181.11,3137.89) 1181.11,3156 cw(c1181.11,3174.11) C31.2@1168.3,3161.3 ; 1241.05,3168.05 ccw(c1221.1,3188) v2@1249.31,3188 ; 1245.88,3172.88 cw(c1259,3159.76) v2@1259,3178.32 ; v2@1253.5,2429.5 1254,2429 1485,2429 1536,2480 v2@2073,2480 ; v2@1259.85,2423.15 cw(c1273.97,2409.03) 1273.97,2429 ; v2@1259.85,2436.85 ccw(c1278.8,2455.8) 1278.8,2429 ; v2@1495,3181.32 cw(c1495,3155.52) 1513.24,3173.76 ; v2@1496,3191 1519,3168 C34.2@1569,3168 ; v2@1504.68,3191 ccw(c1525.65,3191) 1510.83,3176.17 ; C34.2@1563.7,3162.7 ccw(c1550.89,3149.89) 1550.89,3168 ccw(c1550.89,3186.11) C34.2@1563.7,3173.3 ; C35.1@1566,2992 1649,2909 v2(1735,2909) R29.1@1735,3167 ; C34.2@1566,3176 1611,3221 1691,3221 1729,3183 R29.1@1729,3168 ; C35.1@1576.5,3000 ccw(c1621.16,3000) 1589.58,2968.42 ; C34.2@1576.5,3168 cw(c1621.16,3168) 1589.58,3199.58 ; 1705.59,3206.41 cw(c1667.18,3168) R29.1@1721.5,3168 ; R29.1@1723.7,3162.7 cw(c1696.41,3135.41) 1735,3135.41 ; v2@1728.15,2902.15 ccw(c1711.62,2885.62) 1711.62,2909 ccw(c1711.62,2932.38) 1728.15,2915.85 ccw(c1711.62,2932.38) 1735,2932.38 ccw(c1758.38,2932.38) v2@1741.85,2915.85 ; v2@2065.15,2473.15 ccw(c2048.62,2456.62) 2048.62,2480 ccw(c2048.62,2503.38) v2@2065.15,2486.85
  Bottom Layer w10: U2.B9@1291.34,3245.41 1291.34,3296.34 1325,3330 1433,3330 1467.5,3295.5 U2.B4@1467.5,3249.4
  Bottom Layer w20: 1186.18,2392.64 cw(c1253,2325.82) v2@1253,2420.32 ; 1208.82,2415.27 cw(c1232.86,2391.23) v2@1248.54,2421.41 ; 1220.32,2426.78 cw(c1253,2394.11) v2@1253,2440.31 ; JP4.1@1224.32,1834.68 ccw(c1179.22,1879.78) 1243,1879.78 ccw(c1306.78,1879.78) JP4.1@1261.68,1834.68 ; 1228.12,2434.58 cw(c1246.06,2416.64) v2@1257.75,2439.15 ; JP4.1@1243,1816.24 1243,1944 1271,1972 1271,2127 1232,2166 1176,2166 1136,2206 1136,2342.46 1223.54,2430 v2(1253,2430) ; v2@1246.15,2423.15 ccw(c1229.62,2406.62) 1229.62,2430 ccw(c1229.62,2453.38) v2@1246.15,2436.85 ; v2@1259,3187 1283,3210 ; v2@1259.21,3197.68 ccw(c1259.76,3223.52) 1277.64,3204.86 ; v2@1268.68,3187.79 cw(c1289.59,3187.35) 1275.12,3202.45 ; U2.A4@1281.58,3233.61 cw(c1274.46,3226.49) U2.A4@1284.53,3226.49 ; 1284.53,3211.42 U2.A4@1284.53,3249.4 ; U2.A4@1284.53,3226.2 cw(c1295.02,3226.2) U2.B9@1287.6,3233.61 ; U2.B4@1470.55,3233.62 cw(c1463.87,3226.94) U2.B4@1473.32,3226.94 ; 1473.32,3213.68 U2.B4@1473.32,3249.41 ; U2.B4@1473.32,3225.75 cw(c1484.45,3225.75) U2.A9@1476.58,3233.62 ; 1474,3213 v2@1496,3191 ; 1477.76,3209.24 cw(c1459.52,3191) v2@1485.32,3191 ; 1480.17,3206.83 ccw(c1495,3221.65) v2@1495,3200.68 ; v2@1734,2910 1858,2910 ; v2@1741.85,2902.15 cw(c1760.8,2883.2) 1760.8,2910 ; v2@1741.85,2915.85 ccw(c1755.97,2929.97) 1755.97,2910 ; 1912,2910 1858,2910 ; v2@2064.71,2472.71 ccw(c2085.72,2493.72) 2085.72,2464 ; v2@2065.15,2486.85 ccw(c2048.62,2503.38) 2072,2503.38 ccw(c2095.38,2503.38) 2078.85,2486.85 ccw(c2134.01,2542.01) 2134.01,2464 ; v2@2072,2484 2092,2464 2352,2464 2685,2131 2685,1655 CN6.10@2628,1598 ; v2@2072,2485 2072,2773 1935,2910 1858,2910 ; v2@2072.46,2470.33 cw(c2073.82,2441.82) 2094,2462 ; CN6.10@2628,1619.65 ccw(c2628,1671.9) 2664.95,1634.95 ; CN6.10@2654.42,1593.23 cw(c2729.71,1593.23) 2676.47,1646.47
  other v2: 2072,2480 1259,3188 1495,3191
VCC_3V3: CN1.12 CN1.16 CN2.2 CN2.4 JP5.1 R4.2 R12.2 | length 4645.6
  Top Layer w10: v1@1328,2150.19 cw(c1328,2133.75) 1339.63,2145.37 cw(c1351.25,2157) v1@1334.81,2157 ; v1(1328,2157) 1422,2063 1422,1772 JP5.1@1477,1717 ; 1423.5,1770.5 ccw(c1476.91,1823.91) JP5.1@1479.09,1748.4 ; 1428.49,1765.51 cw(c1379.98,1717) JP5.1@1448.58,1717 ; 1439.9,1754.1 ccw(c1477.83,1792.03) JP5.1@1479.38,1738.41 ; JP5.1@1445.56,1748.44 cw(c1414.12,1717) JP5.1@1458.58,1717
  Bottom Layer w10: CN1.16@248,1298 316,1298 ; CN1.12@248,1493.23 313.23,1493.23 ; CN1.16@263.14,1308.37 ccw(c288.19,1333.41) 288.19,1298 ; CN1.12@264.75,1479.88 cw(c292.46,1457.78) 292.46,1493.23 cw(c292.46,1528.68) CN1.12@264.75,1506.58 ; CN1.16@265.77,1281.27 cw(c297.21,1260.09) 297.21,1298 ; CN1.16@270.22,1315.44 ccw(c312.33,1357.56) 312.33,1298 ; CN1.12@272.57,1473.64 cw(c313.22,1441.23) 313.22,1493.23 ; CN1.12@272.57,1512.81 ccw(c313.23,1545.23) 313.23,1493.23 ; CN1.16@274.06,1275.68 cw(c316,1247.44) 316,1298 ; CN2.4@406.78,1288.78 ccw(c353.15,1235.15) 353.15,1311 ccw(c353.15,1386.85) CN2.4@406.78,1333.22 ; CN2.2@406.78,1488.78 ccw(c353.15,1435.15) 353.15,1511 ccw(c353.15,1586.85) CN2.2@406.78,1533.22 ; CN2.4@413.86,1295.86 ccw(c377.29,1259.29) 377.29,1311 ccw(c377.29,1362.71) CN2.4@413.86,1326.14 ; CN2.2@413.86,1495.86 ccw(c377.29,1459.29) 377.29,1511 ccw(c377.29,1562.71) CN2.2@413.86,1526.14 ; CN2.4@427,1298 428,1299 CN2.4@436,1299 ; CN2.4@429,1311 329,1311 316,1298 ; CN2.2@429,1479.58 cw(c429,1403.73) 482.63,1457.37 cw(c536.27,1511) CN2.2@460.42,1511 ; CN2.2@429,1489.58 cw(c429,1437.88) 465.56,1474.44 cw(c502.12,1511) CN2.2@450.42,1511 ; CN2.4@431.86,1322.05 ccw(c441.63,1359.87) 469.25,1332.25 ; CN2.4@434.36,1331.74 ccw(c446.72,1379.53) 481.62,1344.62 ; CN2.4@436.86,1341.42 ccw(c451.8,1399.2) 494,1357 ; CN2.4@438.5,1301.5 494,1357 ; CN2.4@460.42,1311 cw(c490.4,1311) 469.2,1332.2 ; R12.2@1279,2192.5 cw(c1279,2159.91) 1302.04,2182.96 ; R12.2@1279,2205 1386.5,2312.5 1422.5,2312.5 1513,2403 1628,2403 R4.2@1662,2369 ; R12.2@1279,2217.5 ccw(c1279,2247.68) 1300.34,2226.34 ccw(c1321.68,2205) 1291.5,2205 ccw(c1319.26,2205) 1299.63,2185.37 ; R12.2@1285,2200 v1(1328,2157) ; v1@1321.19,2157 ccw(c1304.75,2157) 1316.37,2168.63 ccw(c1328,2180.25) v1@1328,2163.81 ; 1408.69,1620.69 ccw(c1312.38,1717) JP5.1@1448.58,1717 ; 1425.76,1637.76 ccw(c1346.52,1717) JP5.1@1458.58,1717 ; 1442.83,1654.83 ccw(c1380.66,1717) JP5.1@1468.58,1717 ; 1459.9,1671.9 ccw(c1414.81,1717) JP5.1@1478.58,1717 ; JP5.1@1469.05,1681.04 cw(c1480,1670.09) JP5.1@1480,1685.58 ; JP5.1@1477,1717 1477,1689 1331,1543 461,1543 CN2.2@429,1511 ; R4.2@1649.5,2369 ccw(c1619.32,2369) 1640.66,2390.34 ccw(c1662,2411.68) R4.2@1662,2381.5 ; 313.23,1493.23 331,1511 CN2.2@429,1511 ; CN2.2@429,1511 494,1446 494,1422 494,1357
VCC_5V: C26.2 CN1.18 CN2.5 JP4.2 JP4.4 JP4.6 R35.2 U5.3 | length 3630.7
  Top Layer w10: JP4.2@1243,1719 JP4.2@1269,1719
  Top Layer w20: CN2.5@402.58,1211 ccw(c338.81,1211) 383.9,1256.1 ccw(c429,1301.19) CN2.5@429,1237.42 ; CN2.5@423,1227.58 CN2.5@423,1217 ; CN2.5@429,1211 CN2.5@423,1217 ; v2@444.15,1717.15 ccw(c427.62,1700.62) 427.62,1724 ccw(c427.62,1747.38) v2@444.15,1730.85 ; v2(451,1724) 406,1724 372.58,1690.58 372.58,1267.42 CN2.5@423,1217 ; JP4.6@1043,1719 1143,1719 JP4.2@1243,1719 ; JP4.6@1061.68,1697.32 cw(c1114.02,1644.98) JP4.4@1114.02,1719 ; JP4.6@1061.68,1734.68 ccw(c1099.53,1772.53) 1099.53,1719 ; JP4.6@1071.98,1719 cw(c1071.98,1644.98) JP4.4@1124.32,1697.32 ; 1086.47,1719 ccw(c1086.47,1772.53) JP4.4@1124.32,1734.68 ; JP4.4@1161.68,1697.32 cw(c1214.02,1644.98) JP4.2@1214.02,1719 ; JP4.4@1161.68,1734.68 ccw(c1199.53,1772.53) 1199.53,1719 ; JP4.4@1171.98,1719 cw(c1171.98,1644.98) JP4.2@1224.32,1697.32 ; 1186.47,1719 ccw(c1186.47,1772.53) JP4.2@1224.32,1734.68
  Bottom Layer w10: CN2.5@427,1198 CN2.5@428,1199 ; JP4.6@1038,1724 JP4.6@1043,1719 ; JP4.6@1040.24,1716.24 JP4.6@1043,1716.24 ; JP4.2@1243,1719 1257,1719 1305,1767 ; JP4.2@1244.44,1727.33 ccw(c1249.25,1765.08) 1276.17,1738.17 ; JP4.2@1245.71,1737.25 ccw(c1252.51,1790.65) 1290.58,1752.58 ; JP4.2@1246.97,1747.17 ccw(c1255.77,1816.22) 1305,1767 ; JP4.2@1274.42,1716 cw(c1323.71,1716) 1288.85,1750.85 ; 1305,1953.36 cw(c1396.64,1953.36) R35.2@1331.84,2018.16 ; 1305,1977.51 cw(c1372.49,1977.51) R35.2@1324.77,2025.23 ; 1305,2001.65 cw(c1348.35,2001.65) R35.2@1317.7,2032.3 ; R35.2@1323,2027 1322,2027 1305,2010 1305,1767 ; U5.3@1528.45,1932.95 U5.3@1528.45,1954.55
  Bottom Layer w20: CN1.18@248,1193.23 312.23,1193.23 330,1211 CN2.5@429,1211 ; CN1.18@266.68,1174.55 cw(c311.78,1129.45) 311.78,1193.23 cw(c311.78,1257.01) CN1.18@266.68,1211.91 ; CN2.5@410.32,1192.32 ccw(c365.22,1147.22) 365.22,1211 ccw(c365.22,1274.78) CN2.5@410.32,1229.68 ; v2@448,1724 v2(451,1724) 804,1724 869,1659 983,1659 JP4.6@1040.24,1716.24 ; v2@457.85,1717.15 cw(c474.38,1700.62) 474.38,1724 cw(c474.38,1747.38) v2@457.85,1730.85 ; 992.78,1668.78 cw(c1043,1618.56) JP4.6@1043,1689.58 ; 1000.02,1676.02 ccw(c960.05,1716) JP4.6@1016.58,1716 ; R35.2@1323,2027 C26.2@1418,2027 1456,2027 U5.3@1528.45,1954.55 ; R35.2@1328.3,2021.7 cw(c1341.11,2008.89) 1341.11,2027 cw(c1341.11,2045.11) R35.2@1328.3,2032.3 ; C26.2@1412.7,2021.7 ccw(c1399.89,2008.89) 1399.89,2027 ccw(c1399.89,2045.11) C26.2@1412.7,2032.3 ; C26.2@1423.3,2021.7 cw(c1436.11,2008.89) 1436.11,2027 cw(c1436.11,2045.11) C26.2@1423.3,2032.3 ; U5.3@1507.9,1975.1 cw(c1486.42,1953.62) U5.3@1516.8,1953.62 ; U5.3@1510.14,1972.86 ccw(c1528.45,1991.17) U5.3@1528.45,1965.28
VCC_MCU: C1.2 C3.2 C16.1 C18.1 CN1.5 JP1.2 JP6.1 P1.1 R1.2 R3.2 R13.2 R31.1 U1.8 U1.42 | length 8420.3
  Top Layer w10: v1(282,1844) 356,1918 356,2001 392,2037 v1(452,2037) ; v1@282,1850.81 ccw(c282,1867.25) 293.63,1855.63 ccw(c305.25,1844) v1@288.81,1844 ; P1.1@350,3156 495,3156 731,2920 ; P1.1@358.84,3147.16 cw(c380.18,3125.82) 380.18,3156 cw(c380.18,3186.18) P1.1@358.84,3164.84 ; P1.1@365.91,3140.09 cw(c404.32,3101.68) 404.32,3156 cw(c404.32,3210.32) P1.1@365.91,3171.91 ; v1@447.18,2032.18 ccw(c435.56,2020.56) 435.56,2037 ccw(c435.56,2053.44) v1@447.18,2041.82 ; 717,2214 741,2190 ; v1@759.19,2165 ccw(c742.75,2165) 754.37,2176.63 ccw(c766,2188.25) v1@766,2171.81 ; v1@766,2158.19 cw(c766,2141.75) 777.63,2153.37 cw(c789.25,2165) v1@772.81,2165 ; R31.1@812.24,2977.19 ccw(c796,2964.21) 796,2985 ; R31.1@812.24,2992.81 cw(c796,3005.79) 796,2985 ; R31.1@822,2985 796,2985 ; U1.8@1218.57,1012.87 1287.13,1012.87 v1(1295,1005) ; 1259.55,1012.87 cw(c1259.55,969.55) v1@1290.18,1000.18 ; 1283.69,1012.87 cw(c1283.69,993.69) v1@1297.25,1007.25 ; JP1.2@1331.58,1817 ccw(c1255.73,1817) 1309.37,1870.63 ccw(c1363,1924.27) JP1.2@1363,1848.42 ; JP1.2@1341.58,1817 ccw(c1289.88,1817) 1326.44,1853.56 ccw(c1363,1890.12) JP1.2@1363,1838.42 ; JP1.2@1363,1817 1087,2093 838,2093 v1(766,2165) 741,2190 ; U1.42@1539.43,1028.62 1671.38,1028.62 v1(1690,1010) ; v1@1683.19,1010 ccw(c1666.75,1010) 1678.37,1021.63 ccw(c1690,1033.25) v1@1690,1016.81 ; v1@1830,1731.19 cw(c1830,1714.75) 1841.63,1726.37 cw(c1853.25,1738) v1@1836.81,1738 ; v1(1830,1738) 1872,1696 1872,1590 1895,1567 1895,1234 1860,1199 v1(1860,1056) ; v1@1855.18,1060.82 ccw(c1843.56,1072.44) 1860,1072.44 ccw(c1876.44,1072.44) v1@1864.82,1060.82 ; 731,2920 796,2985 ; 731,2920 731,2633 711,2613 711,2220 741,2190
  Bottom Layer w10: CN1.5@148,1793.23 198.77,1844 ; CN1.5@148.85,1814.63 ccw(c150.63,1859.81) 182.61,1827.84 ccw(c214.58,1795.86) CN1.5@169.4,1794.07 ; CN1.5@149.24,1824.62 ccw(c151.86,1890.9) 198.77,1844 ; CN1.5@179.39,1794.47 cw(c245.67,1797.09) 198.77,1844 ; v1@277.18,1839.18 ccw(c265.56,1827.56) 265.56,1844 ccw(c265.56,1860.44) v1@277.18,1848.82 ; v1@282.42,1844 v1(282,1844) 198.77,1844 ; v1(452,2037) 638,2037 v1(766,2165) ; v1@456.82,2032.18 cw(c468.44,2020.56) 468.44,2037 cw(c468.44,2053.44) v1@456.82,2041.82 ; v1@759.19,2165 cw(c742.75,2165) 754.37,2153.37 cw(c766,2141.75) v1@766,2158.19 ; v1@1294.88,1005.12 cw(c1254.76,965) C3.2@1311.5,965 ; v1@1295,998.19 cw(c1295,981.75) 1306.63,993.37 cw(c1318.25,1005) v1@1301.81,1005 ; v1(1295,1005) 1324,976 C3.2@1324,965 C1.2@1324,889 ; 1311.95,988.05 cw(c1288.9,965) C3.2@1321.5,965 ; C1.2@1315.16,891.84 ccw(c1293.82,913.18) 1324,913.18 ccw(c1354.18,913.18) C1.2@1332.84,891.84 ; C3.2@1315.16,956.16 cw(c1293.82,934.82) 1324,934.82 cw(c1354.18,934.82) C3.2@1332.84,956.16 ; C1.2@1316.5,883 ccw(c1351.5,883) 1326.75,858.25 ; C1.2@1324,883 1324,861 ; C1.2@1326.5,883 ccw(c1385.64,883) 1343.82,841.18 ; C1.2@1336.5,883 ccw(c1419.79,883) 1360.89,824.11 ; R1.2@1341,1355 1381,1355 1438,1298 1438,855 R3.2@1384,801 ; R1.2@1349.84,1346.16 cw(c1371.18,1324.82) 1371.18,1355 cw(c1371.18,1385.18) R1.2@1349.84,1363.84 ; JP1.2@1363,1817 JP1.2@1365,1817 ; JP1.2@1364,1818 JP1.2@1365,1817 ; JP1.2@1364.28,1795.62 cw(c1366.79,1753.42) 1396.69,1783.31 cw(c1426.58,1813.21) JP1.2@1384.38,1815.72 ; JP1.2@1364.87,1785.64 cw(c1368.56,1723.73) 1412.42,1767.58 ; R3.2@1371.5,801 ccw(c1341.32,801) 1362.66,822.34 ccw(c1384,843.68) 1384,813.5 ccw(c1384,843.68) 1405.34,822.34 ccw(c1426.68,801) R3.2@1396.5,801 ; R3.2@1392.84,792.16 cw(c1414.18,770.82) 1414.18,801 cw(c1414.18,831.18) R3.2@1392.84,809.84 ; JP1.2@1394.36,1815.13 ccw(c1456.27,1811.44) 1412.42,1767.58 ; JP6.1@1562.83,1753.17 cw(c1531.58,1721.93) JP6.1@1575.64,1718.61 ; JP6.1@1564.28,1751.72 ccw(c1596.4,1783.85) JP6.1@1596.81,1738.42 ; JP6.1@1565.67,1719.36 ccw(c1502.93,1724.09) 1547.42,1768.58 ccw(c1596.11,1817.27) JP6.1@1596.72,1748.42 ; JP6.1@1597,1717 JP6.1@1599,1717 ; JP6.1@1625.55,1703.89 cw(c1646,1694.5) 1646,1717 ; JP6.1@1625.55,1730.11 ccw(c1646,1739.5) 1646,1717 ; v1@1685.18,1005.18 cw(c1673.56,993.56) 1690,993.56 cw(c1706.44,993.56) v1@1694.82,1005.18 ; v1(1690,1010) 1690,973 1709,954 ; C18.1@1725.24,946.19 ccw(c1709,933.21) 1709,954 ; C18.1@1725.24,961.8 cw(c1709,974.78) 1709,954 ; C18.1@1726.16,945.16 cw(c1704.82,923.82) 1735,923.82 cw(c1765.18,923.82) 1743.84,945.16 cw(c1765.18,923.82) 1765.18,954 cw(c1765.18,984.18) C18.1@1743.84,962.84 ; C18.1@1728,952 1729,951 C18.1@1735,951 ; 1784.41,954 ccw(c1784.41,987.59) C16.1@1808.16,963.84 ; 1789.24,954 cw(c1789.24,927.24) C16.1@1808.16,946.16 ; C16.1@1817,954 C18.1@1735,954 ; C16.1@1817,955 R13.2@1900,955 1860,995 v1(1860,1056) ; v1@1825.18,1733.18 ccw(c1813.56,1721.56) 1813.56,1738 ccw(c1813.56,1754.44) v1@1825.18,1742.82 ; C16.1@1825.84,946.16 cw(c1847.18,924.82) 1847.18,955 cw(c1847.18,985.18) C16.1@1825.84,963.84 ; v1(1830,1738) 1783,1738 1734.5,1689.5 1673.5,1689.5 1646,1717 ; v1@1855.18,1051.18 cw(c1843.56,1039.56) 1860,1039.56 cw(c1876.44,1039.56) v1@1864.82,1051.18 ; R13.2@1887.5,955 ccw(c1857.32,955) 1878.66,976.34 ccw(c1900,997.68) R13.2@1900,967.5 ; R13.2@1891.16,946.16 ccw(c1869.82,924.82) 1869.82,955 ccw(c1869.82,985.18) R13.2@1891.16,963.84 ; 1324,861 cw(c1337.1,861) 1330.4,872.26 ccw(c1337.1,861) 1324,861 ; 1324,861 ccw(c1310.89,861) 1317.6,872.26 cw(c1310.89,861) 1324,861 ; 1324,861 R3.2@1384,801 ; JP1.2@1365,1817 1365,1815 1412.42,1767.58 ; R3.2@1384,801 1618,801 1735,918 C18.1@1735,951 ; 1412.42,1767.58 1548.42,1767.58 JP6.1@1599,1717 ; JP6.1@1599,1717 1646,1717 ; 1709,954 C18.1@1735,954 ; C18.1@1735,951 C18.1@1735,954
VCORE: C4.1 C9.1 U1.6 | length 290.7
  Top Layer w10: U1.6@1218.57,1044.37 1277.37,1044.37 v1(1324,1091) ; v1@1317.19,1091 cw(c1300.75,1091) 1312.37,1079.37 cw(c1324,1067.75) v1@1324,1084.19
  Bottom Layer w10: C4.1@1321,1126 C4.1@1324,1129
  Bottom Layer w20: C9.1@1318.7,1052.3 ccw(c1305.89,1065.11) 1324,1065.11 ccw(c1342.11,1065.11) C9.1@1329.3,1052.3 ; C4.1@1318.7,1123.7 cw(c1305.89,1110.89) 1324,1110.89 cw(c1342.11,1110.89) C4.1@1329.3,1123.7 ; C9.1@1324,1047 C4.1@1324,1126
VDD_LINK: C20.2 C21.2 C29.1 C32.1 D5.2 D5.4 R30.1 R31.2 U3.12 U3.13 U3.20 U3.31 | length 3388.4
  Top Layer w10: R31.2@882,2985 921,3024 1089,3024 C29.1@1161.5,2951.5 ; R31.2@882,2997.5 ccw(c882,3027.68) 903.34,3006.34 ccw(c924.68,2985) R31.2@894.5,2985 ; 1136.54,2976.46 ccw(c1163,3002.92) C29.1@1163,2965.5 ; 1143.78,2969.22 cw(c1127.57,2953) C29.1@1150.5,2953 ; C29.1@1163,2953 1207,2953 1214.84,2960.84 ; C29.1@1171.84,2944.16 cw(c1193.18,2922.82) 1193.18,2953 cw(c1193.18,2983.18) C29.1@1171.84,2961.84 ; 1208.34,2954.34 cw(c1218.04,2944.65) v1@1225.36,2956.24 ; 1214.25,2960.25 cw(c1226.65,2947.85) v1@1229.52,2965.15 ; 1215.35,2960.84 cw(c1215.35,2948.35) v1@1224.18,2957.18 ; 1217.19,2963.19 cw(c1224.89,2955.49) v1@1230.7,2964.7 ; v1@1223.18,2965.53 cw(c1214.84,2970.59) 1214.84,2960.84 ; v1@1233.82,2957.18 cw(c1242.65,2948.35) 1242.65,2960.84 ; v1@1233.82,2966.82 ccw(c1248.24,2981.24) 1248.24,2960.84 ; U3.20@1278.61,2960.84 1214.84,2960.84 ; C21.2@1369,2763 1459,2763 v1@1459,2792 ; U3.13@1369.16,3051.39 1369.16,3088.16 1376,3095 ; 1370.5,3089.5 cw(c1381.75,3078.25) v1@1388.23,3092.78 ; 1378.63,3097.63 cw(c1389.78,3086.48) v1@1391.31,3102.17 ; C21.2@1382.84,2753.16 cw(c1406.59,2729.41) 1406.59,2763 ; C21.2@1382.84,2770.84 ccw(c1401.76,2789.76) 1401.76,2763 ; v1@1384.54,3101.15 cw(c1376,3104) 1376,3095 ; U3.12@1388.84,3051.39 v1@1388.84,3092.84 ; 1388.84,3077.35 cw(c1412.65,3077.35) v1@1395.82,3094.18 ; v1@1391,3095 1376,3095 ; v1@1391,3097 1422,3128 1521,3128 C32.1@1564,3085 ; v1@1391,3105.81 ccw(c1391,3127.08) 1406.04,3112.04 ; v1@1397.81,3099 cw(c1409.43,3099) 1401.21,3107.21 ; 1426.41,2763 cw(c1426.41,2729.41) C20.2@1450.16,2753.16 ; U3.31@1428.21,2850.61 1428.21,2822.79 v1(1451,2800) v1@1459,2792 ; 1431.24,2763 ccw(c1431.24,2789.76) C20.2@1450.16,2770.84 ; v1@1444.19,2800 ccw(c1427.75,2800) 1439.37,2811.63 ccw(c1451,2823.25) v1@1451,2806.81 ; v1@1446.18,2795.18 cw(c1415.24,2764.24) C20.2@1459,2764.24 ; C20.2@1450.2,2770.88 ccw(c1429.25,2792) v1@1459,2792 ; v1@1453.25,2802.25 cw(c1439.38,2788.38) 1459,2788.38 ; C20.2@1467.8,2770.88 cw(c1488.75,2792) v1@1459,2792 ; 1544.25,3104.75 ccw(c1569,3129.5) C32.1@1569,3094.5 ; 1549.08,3099.92 cw(c1531.15,3082) C32.1@1556.5,3082 ; C32.1@1560.16,3073.16 cw(c1543.65,3056.65) v1@1567,3056.65 ; v1@1562.18,3055.82 ccw(c1550.56,3067.44) 1567,3067.44 ccw(c1583.44,3067.44) v1@1571.82,3055.82 ; v1@1567,3050.94 cw(c1595.02,3050.94) C32.1@1577.03,3072.42 ; v1(1567,3051) C32.1@1567,3084 ; v1@2169.3,3195.69 cw(c2176.59,3184.16) 2186.24,3193.81 ; v1@2171,3186.19 cw(c2171,3130.99) 2210.03,3170.02 ; v1(2171,3193) 2187.06,3193 ; v1@2171,3196.19 cw(c2171,3165.13) 2192.96,3187.09 ; v1@2174.64,3187.24 cw(c2183.44,3173.33) 2195.08,3184.97 ; v1@2175.9,3188.27 cw(c2187.05,3177.48) 2187.05,3193 ; v1@2175.9,3197.73 ccw(c2187.05,3208.52) 2187.05,3193 ; 2209.65,3170.4 ccw(c2228,3188.75) D5.2@2228,3162.8 ; D5.2@2216.78,3163.27 cw(c2208.51,3155.01) D5.2@2220.2,3155.01 ; D5.2@2228,3152.06 2187.06,3193
  Bottom Layer w10: v1@1224.18,2966.82 ccw(c1212.56,2978.44) 1229,2978.44 ccw(c1245.44,2978.44) v1@1233.82,2966.82 ; v1(1229,2962) 1229,2984 1264,3019 1365,3019 1391,3045 v1(1391,3099) ; v1@1386.18,3094.18 cw(c1374.56,3082.56) 1391,3082.56 cw(c1407.44,3082.56) v1@1395.82,3094.18 ; v1@1451,2799 1479,2827 1479,3013 1517,3051 v1(1567,3051) ; v1@1451,2806.81 ccw(c1451,2825.67) 1464.33,2812.33 ; v1@1457.81,2800 cw(c1471.84,2800) 1461.92,2809.92 ; R30.1@1556.55,3027.21 ccw(c1534.7,3051) v1(1567,3051) ; v1@1562.18,3055.82 cw(c1550.56,3067.44) 1550.56,3051 cw(c1550.56,3034.56) 1562.18,3046.18 cw(c1550.55,3034.55) 1567,3034.55 cw(c1583.44,3034.56) 1571.82,3046.18 cw(c1583.44,3034.56) 1583.44,3051 cw(c1583.44,3067.44) v1@1571.82,3055.82 ; R30.1@1565,3018 R30.1@1567,3020 ; R30.1@1567,3018 v1(1567,3051) ; v1@1567,3043.35 ccw(c1590.35,3043.35) R30.1@1573.84,3026.84 ; v1@2166.18,3188.18 ccw(c2154.56,3176.56) 2154.56,3193 ccw(c2154.56,3209.44) v1@2166.18,3197.82 ; v1(2171,3193) 2122,3193 1980,3051 v1(1567,3051)
VIN: C23.2 CN1.24 CN2.8 U4.3 | length 2392.4
  Top Layer w10: CN2.8@423,899 CN2.8@428,899
  Top Layer w20: 336,981.94 336,998 ; CN2.8@407.18,896.11 ccw(c379,876.89) 379,911 ; CN2.8@407.18,925.89 cw(c379,945.11) 379,911 ; CN2.8@418.47,900.47 419.94,899 CN2.8@423,899 ; CN2.8@429,911 379,911 ; v2@450.32,1946 cw(c426.93,1946) 443.47,1929.47 cw(c460,1912.93) v2@460,1936.32 ; v2(460,1946) 336,1822 336,998 ; 336,998 336,954 379,911
  Bottom Layer w10: C23.2@778,2020 C23.2@778,2027 ; U4.3@874,1909 U4.3@876,1911
  Bottom Layer w20: CN1.24@248,893.23 324.23,893.23 337.23,893.23 355,911 CN2.8@429,911 ; CN1.24@266.68,874.55 cw(c311.78,829.45) 311.78,893.23 cw(c311.78,957.01) CN1.24@266.68,911.91 ; CN2.8@410.32,892.32 ccw(c365.22,847.22) 365.22,911 ccw(c365.22,974.78) CN2.8@410.32,929.68 ; v2@459,1946 v2(460,1946) 620,1946 671,1946 704,1913 U4.3@873,1913 ; v2@466.85,1939.15 cw(c483.38,1922.62) 483.38,1946 cw(c483.38,1969.38) v2@466.85,1952.85 ; C23.2@783.3,2021.7 cw(c796.11,2008.89) 796.11,2027 cw(c796.11,2045.11) C23.2@783.3,2032.3 ; C23.2@785,2020 C23.2@778,2027 814,2027 U4.3@880.45,1960.55 ; 841.98,1913 ccw(c841.98,1955.75) U4.3@872.21,1925.52 ; 859.19,1981.81 cw(c836,1958.62) U4.3@868.8,1958.62 ; U4.3@863.85,1977.15 ccw(c880.45,1993.75) U4.3@880.45,1970.28
VIN_5V: C25.2 JP4.3 R24.1 U4.2 | length 1775.3
  Bottom Layer w10: R24.1@625,1598.5 cw(c625,1568.32) 646.34,1589.66 cw(c667.68,1611) R24.1@637.5,1611 ; R24.1@625,1604 632,1604 663,1573 1040,1573 1093.58,1626.58 1093.58,1766.58 ; U4.2@971,1900.63 cw(c971,1861.11) 998.95,1889.05 ; U4.2@971,1917 U4.2@971,1937.95 ; U4.2@973,1915 1013,1875 1060,1875 1084,1875 JP4.3@1143,1816 1093.58,1766.58 ; U4.2@987.65,1917.28 ccw(c1028.54,1917.28) 999.63,1888.37 ; JP4.3@1111.58,1816 ccw(c1035.73,1816) 1089.37,1869.63 ccw(c1143,1923.27) JP4.3@1143,1847.42 ; JP4.3@1111.64,1814.13 cw(c1049.73,1810.44) 1093.58,1766.58 ; JP4.3@1121.62,1814.72 cw(c1079.42,1812.21) 1109.31,1782.31 cw(c1139.21,1752.42) JP4.3@1141.72,1794.62 ; JP4.3@1121.58,1816 ccw(c1069.88,1816) 1106.44,1852.56 ccw(c1143,1889.12) JP4.3@1143,1837.42 ; JP4.3@1141.13,1784.64 ccw(c1137.44,1722.73) 1093.58,1766.58
  Bottom Layer w20: U4.2@971,1937.95 971,1966 1092,2087 C25.2@1171,2087 ; U4.2@982.65,1958.62 cw(c1028.6,1958.62) 996.11,1991.11 ; C25.2@1165.7,2081.7 ccw(c1152.89,2068.89) 1152.89,2087 ccw(c1152.89,2105.11) C25.2@1165.7,2092.3
pads on no net: U2. U2.A5 U2.A8 U2.B5 U2.B8 U3.1 U3.4 U3.8 U3.9 U3.10 U3.16 U3.18 U3.19 U3.27 U3.28 U3.29 U3.30 U4.4 U5.4 Y2.12

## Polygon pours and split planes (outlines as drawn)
GND on Top Layer "Top Layer-No Net" (solid, pour order 1000): 216 vertices, not listed, extent 0,0 2756,3548
GND on Bottom Layer "Top Layer-No Net" (solid, remove dead copper, pour order 1001): 259 vertices, not listed, extent 0,0 2756,3548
